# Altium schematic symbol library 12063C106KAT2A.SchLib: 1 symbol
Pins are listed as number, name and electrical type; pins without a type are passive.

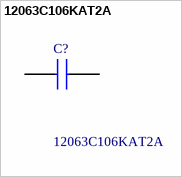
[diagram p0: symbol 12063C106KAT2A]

## 12063C106KAT2A
designator C?
MLCC Capacitor 10uF 1206 X7R 10% 25V AVX 10uF Ceramic Multilayer Capacitor 25 V +/-10% X7R dielectric FlEXITERM SMT max op. temp. +125C; Manufacturer_Name: Kyocera AVX; Geometry.Height: 2.29mm
footprint CAPC3216X229N
pins: 1, 2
